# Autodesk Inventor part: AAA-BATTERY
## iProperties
Shininess: 20.0
Length Units: 11272
Angle Units: 11279
Time Units: 11290
Mass Units: 11286
Length Display Precision: 3
Angle Display Precision: 2
Created: 2001-05
Part Number: AAA-BATTERY
Document SubType Name: Modeling
Designer: Ron Crain
Catalog Web Link: http://www.arken.net
Density: 0.0
Volumn: 0.0
Area: 0.0
PropertySet Name: Model Information
Control State: 0
Master: False
Checked Out: False
Author: Ron
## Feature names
1. Revolution1
2. Fillet1
3. Extrusion1
4. Fillet2
5. Extrusion2
